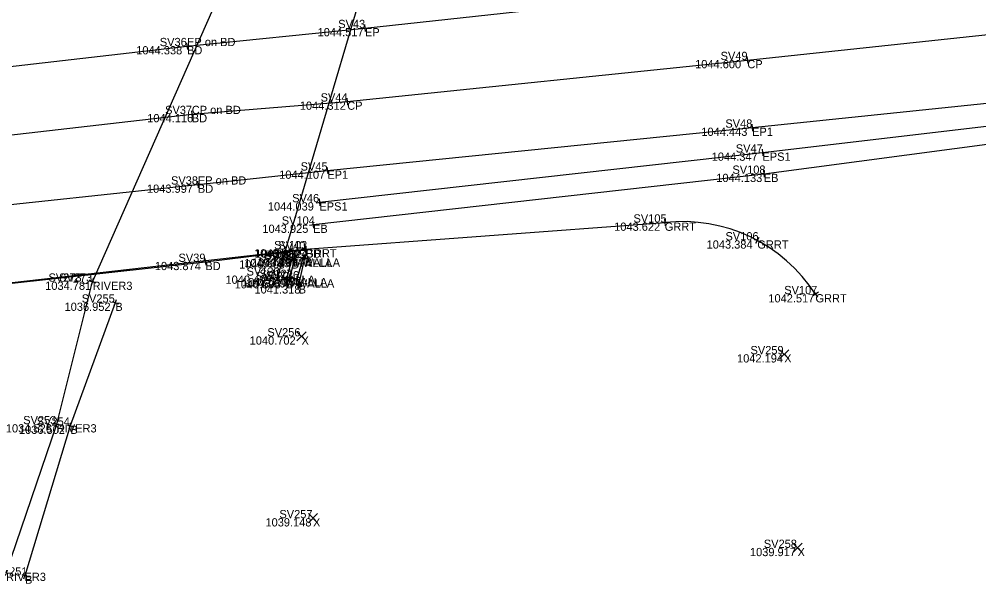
# Model space of a CAD drawing. Extents: x 1542529 to 1609210, y 587215 to 645373.
# Drawn here: x 1608930.2 to 1609069.9, y 645186.6 to 645268.8 of the extents above; entities that cross this region are included whole.
import ezdxf

# ---------------------------------------------------------------- set-up
doc = ezdxf.new("R2010")
doc.units = 0
for name, color, linetype in [('BR_X_SV_Abut', 7, 'Continuous'), ('BR_X_SV_Abut_Text', 7, 'Continuous'), ('BR_X_SV_Deck_Top', 7, 'Continuous'), ('BR_X_SV_Deck_Top_Text', 7, 'Continuous'), ('HY_X_Water_Edge', 7, 'Continuous'), ('PV_X_COP', 7, 'Continuous'), ('PV_X_EOP', 7, 'Continuous'), ('PV_X_Shoulder', 7, 'Continuous'), ('PV_X_Shoulder_Aggregate', 7, 'Continuous'), ('RD_X_GR_Rt', 7, 'Continuous'), ('SV_X_Break_Lines', 7, 'Continuous'), ('SV_X_Random_Point', 7, 'Continuous'), ('SV_X_Shot_Marker', 7, 'Continuous'), ('SV_X_Text_Comment', 7, 'Continuous'), ('SV_X_Text_Elevation', 7, 'Continuous'), ('SV_X_Text_Name', 7, 'Continuous')]:
    doc.layers.add(name, color=color, linetype=linetype)

msp = doc.modelspace()

# ---------------------------------------------------------------- linework, layer by layer
at = {"layer": 'BR_X_SV_Abut'}
for points in [[(1608983.32, 645283.77), (1608967.84, 645231.45)], [(1608971.48, 645233.94), (1608970.63, 645230.91), (1608969.63, 645231.1), (1608970.33, 645233.87)]]:
    msp.add_lwpolyline(points, dxfattribs=at)
at = {"layer": 'BR_X_SV_Abut_Text'}
for p, q in [((1608969.84, 645233.99), (1608970.81, 645233.74)), ((1608970.2, 645233.38), (1608970.45, 645234.35)), ((1608970.33, 645233.87), (1608970.33, 645233.87)), ((1608971.96, 645233.81), (1608971, 645234.08)), ((1608971.61, 645234.42), (1608971.34, 645233.46)), ((1608971.48, 645233.94), (1608971.48, 645233.94)), ((1608967.98, 645231.93), (1608967.7, 645230.97)), ((1608968.32, 645231.31), (1608967.36, 645231.59)), ((1608967.84, 645231.45), (1608967.84, 645231.45)), ((1608970.12, 645231.01), (1608969.14, 645231.2)), ((1608969.53, 645230.61), (1608969.72, 645231.6)), ((1608969.63, 645231.1), (1608969.63, 645231.1)), ((1608971.11, 645230.78), (1608970.15, 645231.05)), ((1608970.76, 645231.4), (1608970.49, 645230.43)), ((1608970.63, 645230.91), (1608970.63, 645230.91))]:
    msp.add_line(p, q, dxfattribs=at)
at = {"layer": 'BR_X_SV_Deck_Top'}
for points in [[(1608887.49, 645257.66), (1608918.33, 645260.66), (1608954.65, 645264.83), (1608980.54, 645267.46)], [(1608884.55, 645247.04), (1608919.35, 645250.82), (1608955.34, 645254.95), (1608977.96, 645256.77)], [(1608881.41, 645236.41), (1608919.82, 645240.81), (1608956.22, 645244.69), (1608975.06, 645246.73)], [(1608877.31, 645224.5), (1608921.25, 645229.45), (1608957.31, 645233.44), (1608971.94, 645235.23)]]:
    msp.add_lwpolyline(points, dxfattribs=at)
at = {"layer": 'BR_X_SV_Deck_Top_Text'}
for p, q in [((1608954.16, 645264.77), (1608955.15, 645264.89)), ((1608954.59, 645265.33), (1608954.71, 645264.34)), ((1608954.65, 645264.83), (1608954.65, 645264.83)), ((1608954.84, 645254.89), (1608955.83, 645255)), ((1608955.28, 645255.44), (1608955.39, 645254.45)), ((1608955.34, 645254.95), (1608955.34, 645254.95)), ((1608955.72, 645244.64), (1608956.71, 645244.75)), ((1608956.16, 645245.19), (1608956.27, 645244.2)), ((1608956.22, 645244.69), (1608956.22, 645244.69)), ((1608971.44, 645235.17), (1608972.44, 645235.29)), ((1608971.88, 645235.73), (1608972, 645234.74)), ((1608971.94, 645235.23), (1608971.94, 645235.23)), ((1608956.81, 645233.39), (1608957.8, 645233.5)), ((1608957.25, 645233.94), (1608957.36, 645232.95)), ((1608957.31, 645233.44), (1608957.31, 645233.44))]:
    msp.add_line(p, q, dxfattribs=at)
at = {"layer": 'HY_X_Water_Edge'}
for points in [[(1608959.88, 645339.77), (1608945.44, 645307.64), (1608946.45, 645304.79), (1608971.33, 645299.45), (1608940.9, 645230.56)], [(1608928.31, 645188.21), (1608935.69, 645209.82), (1608940.9, 645230.56)]]:
    msp.add_lwpolyline(points, dxfattribs=at)
at = {"layer": 'PV_X_COP'}
msp.add_lwpolyline([(1608977.96, 645256.77), (1609036.2, 645262.81), (1609089.9, 645268.52), (1609144.66, 645274.29), (1609196.98, 645279.72)], dxfattribs=at)
at = {"layer": 'PV_X_EOP'}
for points in [[(1608980.54, 645267.46), (1609035.11, 645273.39), (1609089.32, 645279.34), (1609143.54, 645285.01), (1609196.2, 645290.63)], [(1608975.06, 645246.73), (1609036.89, 645252.97), (1609090.69, 645258.56), (1609145.51, 645264.11), (1609197.96, 645269.81)]]:
    msp.add_lwpolyline(points, dxfattribs=at)
at = {"layer": 'PV_X_Shoulder'}
msp.add_lwpolyline([(1608973.91, 645242.11), (1609038.4, 645249.35), (1609090.83, 645255.49), (1609115.31, 645257.8), (1609116.26, 645256.18), (1609146.72, 645259.79), (1609175.76, 645262.45), (1609187.79, 645262.63), (1609192.1, 645261.8), (1609200.06, 645262.49)], dxfattribs=at)
at = {"layer": 'PV_X_Shoulder_Aggregate'}
msp.add_lwpolyline([(1608972.98, 645238.86), (1609038.59, 645246.26), (1609094.1, 645253.6), (1609115.99, 645255.67)], dxfattribs=at)
at = {"layer": 'RD_X_GR_Rt'}
for p, q in [((1608971.87, 645235.28), (1609024.18, 645239.16)), ((1608876.93, 645224.49), (1608971.87, 645235.28))]:
    msp.add_line(p, q, dxfattribs=at)
msp.add_arc((1609026.75, 645216.26), 23.04, 32.7693, 96.3936, dxfattribs=at)
at = {"layer": 'SV_X_Break_Lines'}
for points in [[(1608969.83, 645233.67), (1608969.06, 645230.78), (1608970.9, 645230.03), (1608971.78, 645234.03)], [(1608931.06, 645187.8), (1608937.66, 645209.61), (1608944.21, 645227.51)]]:
    msp.add_lwpolyline(points, dxfattribs=at)
at = {"layer": 'SV_X_Random_Point'}
for p, q in [((1608970.64, 645221.93), (1608971.97, 645223.26)), ((1608970.64, 645223.26), (1608971.97, 645221.93)), ((1609040.9, 645219.33), (1609042.23, 645220.66)), ((1609040.9, 645220.66), (1609042.23, 645219.33)), ((1608972.32, 645195.48), (1608973.65, 645196.81)), ((1608972.32, 645196.81), (1608973.65, 645195.48)), ((1609042.84, 645191.15), (1609044.17, 645192.49)), ((1609042.84, 645192.49), (1609044.17, 645191.15))]:
    msp.add_line(p, q, dxfattribs=at)
at = {"layer": 'SV_X_Shot_Marker'}
for p, q in [((1608980.04, 645267.41), (1608981.03, 645267.51)), ((1608980.49, 645267.96), (1608980.59, 645266.96)), ((1608980.54, 645267.46), (1608980.54, 645267.46)), ((1609035.7, 645262.76), (1609036.7, 645262.86)), ((1609036.15, 645263.31), (1609036.25, 645262.31)), ((1609036.2, 645262.81), (1609036.2, 645262.81)), ((1608977.92, 645257.26), (1608978, 645256.27)), ((1608977.46, 645256.73), (1608978.46, 645256.81)), ((1608977.96, 645256.77), (1608977.96, 645256.77)), ((1609036.4, 645252.92), (1609037.39, 645253.02)), ((1609036.84, 645253.47), (1609036.94, 645252.47)), ((1609036.89, 645252.97), (1609036.89, 645252.97)), ((1609037.9, 645249.3), (1609038.9, 645249.41)), ((1609038.35, 645249.85), (1609038.46, 645248.86)), ((1609038.4, 645249.35), (1609038.4, 645249.35)), ((1608974.57, 645246.68), (1608975.56, 645246.78)), ((1608975.01, 645247.23), (1608975.12, 645246.23)), ((1608975.06, 645246.73), (1608975.06, 645246.73)), ((1609038.09, 645246.21), (1609039.08, 645246.32)), ((1609038.53, 645246.76), (1609038.64, 645245.77)), ((1609038.59, 645246.26), (1609038.59, 645246.26)), ((1608973.42, 645242.05), (1608974.41, 645242.16)), ((1608973.86, 645242.6), (1608973.97, 645241.61)), ((1608973.91, 645242.11), (1608973.91, 645242.11)), ((1608972.48, 645238.8), (1608973.47, 645238.91)), ((1608972.92, 645239.35), (1608973.03, 645238.36)), ((1609023.68, 645239.11), (1609024.68, 645239.22)), ((1609024.12, 645239.66), (1609024.24, 645238.67)), ((1609024.18, 645239.16), (1609024.18, 645239.16)), ((1608972.98, 645238.86), (1608972.98, 645238.86)), ((1609037.21, 645236.8), (1609038.09, 645236.33)), ((1609037.88, 645237.01), (1609037.41, 645236.13)), ((1609037.65, 645236.57), (1609037.65, 645236.57)), ((1608971.37, 645235.24), (1608972.37, 645235.32)), ((1608971.84, 645235.78), (1608971.91, 645234.78)), ((1608971.87, 645235.28), (1608971.87, 645235.28)), ((1608970.31, 645233.54), (1608969.35, 645233.8)), ((1608969.96, 645234.15), (1608969.7, 645233.19)), ((1608969.83, 645233.67), (1608969.83, 645233.67)), ((1608971.29, 645234.14), (1608972.26, 645233.92)), ((1608971.67, 645233.54), (1608971.88, 645234.52)), ((1608971.78, 645234.03), (1608971.78, 645234.03)), ((1608940.41, 645230.69), (1608941.38, 645230.44)), ((1608941.35, 645230.36), (1608940.44, 645230.77)), ((1608941.1, 645231.02), (1608940.69, 645230.11)), ((1608940.77, 645230.08), (1608941.02, 645231.05)), ((1608940.9, 645230.56), (1608940.9, 645230.56)), ((1608940.9, 645230.56), (1608940.9, 645230.56)), ((1608969.54, 645230.65), (1608968.57, 645230.91)), ((1608969.19, 645231.26), (1608968.93, 645230.29)), ((1608969.06, 645230.78), (1608969.06, 645230.78)), ((1608970.43, 645230.22), (1608971.36, 645229.84)), ((1608971.09, 645230.49), (1608970.71, 645229.57)), ((1608970.9, 645230.03), (1608970.9, 645230.03)), ((1609045.85, 645229.16), (1609046.39, 645228.32)), ((1608944.04, 645227.04), (1608944.38, 645227.98)), ((1609046.54, 645229.01), (1609045.7, 645228.47)), ((1609046.12, 645228.74), (1609046.12, 645228.74)), ((1608943.74, 645227.68), (1608944.68, 645227.34)), ((1608944.21, 645227.51), (1608944.21, 645227.51)), ((1608935.22, 645209.98), (1608936.17, 645209.66)), ((1608935.53, 645209.35), (1608935.85, 645210.3)), ((1608935.69, 645209.82), (1608935.69, 645209.82)), ((1608937.18, 645209.75), (1608938.14, 645209.46)), ((1608937.51, 645209.13), (1608937.8, 645210.09)), ((1608937.66, 645209.61), (1608937.66, 645209.61)), ((1608930.58, 645187.94), (1608931.53, 645187.65)), ((1608930.91, 645187.32), (1608931.2, 645188.28)), ((1608931.06, 645187.8), (1608931.06, 645187.8))]:
    msp.add_line(p, q, dxfattribs=at)

# ---------------------------------------------------------------- texts
at = {"layer": 'BR_X_SV_Abut_Text'}
for s, p in [('SV128', (1608965.89, 645233.87)), ('SV125', (1608967.06, 645233.94)), ('1043.789', (1608962.97, 645232.67)), ('1043.763', (1608964.11, 645232.74)), ('WALLA', (1608970.33, 645232.67)), ('WALLA', (1608971.48, 645232.74)), ('SV120', (1608963.31, 645231.45)), ('SV127', (1608965.21, 645231.1)), ('SV126', (1608966.13, 645230.91)), ('1040.409', (1608960.24, 645230.25)), ('1043.710', (1608962.65, 645229.9)), ('1043.697', (1608963.22, 645229.71)), ('WALLA', (1608967.84, 645230.25)), ('WALLA', (1608969.63, 645229.9)), ('WALLA', (1608970.63, 645229.71))]:
    msp.add_text(s, height=1.2, dxfattribs=at).set_placement(p)
at = {"layer": 'BR_X_SV_Deck_Top_Text'}
for s, p in [('SV36', (1608950.68, 645264.83)), ('EP on BD', (1608954.65, 645264.83)), ('1044.338', (1608947.25, 645263.63)), ('BD', (1608954.65, 645263.63)), ('SV37', (1608951.45, 645254.95)), ('CP on BD', (1608955.34, 645254.95)), ('1044.116', (1608948.85, 645253.75)), ('BD', (1608955.34, 645253.75)), ('SV38', (1608952.31, 645244.69)), ('EP on BD', (1608956.22, 645244.69)), ('1043.997', (1608948.81, 645243.49)), ('BD', (1608956.22, 645243.49)), ('SV40', (1608967.95, 645235.23)), ('1043.952', (1608964.56, 645234.03)), ('BD', (1608971.94, 645234.03)), ('1043.874', (1608949.96, 645232.24)), ('SV39', (1608953.4, 645233.44)), ('BD', (1608957.31, 645232.24))]:
    msp.add_text(s, height=1.2, dxfattribs=at).set_placement(p)
at = {"layer": 'SV_X_Text_Comment'}
for s, p in [('EP', (1608980.54, 645266.26)), ('CP', (1609036.2, 645261.61)), ('CP', (1608977.96, 645255.57)), ('EP1', (1609036.89, 645251.77)), ('EPS1', (1609038.4, 645248.15)), ('EP1', (1608975.06, 645245.53)), ('EB', (1609038.59, 645245.06)), ('EPS1', (1608973.91, 645240.91)), ('GRRT', (1609024.18, 645237.96)), ('EB', (1608972.98, 645237.66)), ('GRRT', (1609037.65, 645235.37)), ('GRRT', (1608971.87, 645234.08)), ('B', (1608969.83, 645232.47)), ('B', (1608971.78, 645232.83)), ('RIVER3', (1608940.9, 645229.36)), ('RIVER', (1608940.9, 645229.36)), ('B', (1608969.06, 645229.58)), ('B', (1608970.9, 645228.83)), ('GRRT', (1609046.12, 645227.54)), ('B', (1608944.21, 645226.31)), ('X', (1608971.31, 645221.4)), ('X', (1609041.56, 645218.8)), ('RIVER3', (1608935.69, 645208.62)), ('B', (1608937.66, 645208.41)), ('X', (1608972.98, 645194.94)), ('X', (1609043.51, 645190.62)), ('RIVER3', (1608928.31, 645187.01)), ('B', (1608931.06, 645186.6))]:
    msp.add_text(s, height=1.2, dxfattribs=at).set_placement(p)
at = {"layer": 'SV_X_Text_Elevation'}
for s, p in [('1044.517', (1608973.65, 645266.26)), ('1044.600', (1609028.6, 645261.61)), ('1044.312', (1608971.06, 645255.57)), ('1044.443', (1609029.51, 645251.77)), ('1044.347', (1609031.01, 645248.15)), ('1044.107', (1608968.06, 645245.53)), ('1044.133', (1609031.68, 645245.06)), ('1044.039', (1608966.41, 645240.91)), ('1043.622', (1609016.82, 645237.96)), ('1043.925', (1608965.61, 645237.66)), ('1043.384', (1609030.27, 645235.37)), ('1043.420', (1608964.41, 645234.08)), ('1040.409', (1608962.23, 645232.47)), ('1042.914', (1608964.91, 645232.83)), ('1034.781', (1608934, 645229.36)), ('1034.781', (1608934, 645229.36)), ('1040.595', (1608961.58, 645229.58)), ('1041.318', (1608964.46, 645228.83)), ('1042.517', (1609039.26, 645227.54)), ('1036.952', (1608936.82, 645226.31)), ('1040.702', (1608963.76, 645221.4)), ('1042.194', (1609034.7, 645218.8)), ('1034.526', (1608928.27, 645208.62)), ('1036.502', (1608930.18, 645208.41)), ('1039.148', (1608966.06, 645194.94)), ('1039.917', (1609036.58, 645190.62))]:
    msp.add_text(s, height=1.2, dxfattribs=at).set_placement(p)
at = {"layer": 'SV_X_Text_Name'}
for s, p in [('SV43', (1608976.65, 645267.46)), ('SV49', (1609032.31, 645262.81)), ('SV44', (1608974.09, 645256.77)), ('SV48', (1609033, 645252.97)), ('SV47', (1609034.52, 645249.35)), ('SV45', (1608971.18, 645246.73)), ('SV108', (1609034.03, 645246.26)), ('SV46', (1608969.95, 645242.11)), ('SV105', (1609019.63, 645239.16)), ('SV104', (1608968.43, 645238.86)), ('SV106', (1609033.02, 645236.57)), ('SV103', (1608967.32, 645235.28)), ('SV121', (1608965.86, 645233.67)), ('SV124', (1608967.36, 645234.03)), ('SV122', (1608964.65, 645230.78)), ('SV273_1', (1608934.48, 645230.56)), ('SV273', (1608936.02, 645230.56)), ('SV123', (1608966.48, 645230.03)), ('SV107', (1609041.57, 645228.74)), ('SV255', (1608939.31, 645227.51)), ('SV256', (1608966.34, 645222.6)), ('SV259', (1609036.66, 645220)), ('SV253', (1608930.8, 645209.82)), ('SV254', (1608932.77, 645209.61)), ('SV257', (1608968.09, 645196.14)), ('SV258', (1609038.6, 645191.82)), ('SV251', (1608926.61, 645187.8))]:
    msp.add_text(s, height=1.2, dxfattribs=at).set_placement(p)

doc.saveas('drawing.dxf')
